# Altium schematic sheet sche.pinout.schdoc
size 297 x 209 mm; Width: 1170; Height: 825; Symbol: Sheet-Symbol_A4; Company: 嘉立创EDA; Version: V1.0; Page Size: A4; @Project Name: 木马派(Mumap) Linux卡片电脑-RV1106G; @Page Count: 10; @Update Date: 2024-12-29; @Create Date: 2024-11-25; @Schematic Name: Schematic1; @Page No: 5; Border: 1; Title Block Position: 3; Region Start: 1; X Region Count: 6; Y Region Count: 4; Blade Width: 10; Title Block: 1; @Board Name: NandFlash; @Create Time: 22:45:07; @Update Time: 16:11:56; @Page Name: FEPHY; Device: Sheet-Symbol_A4
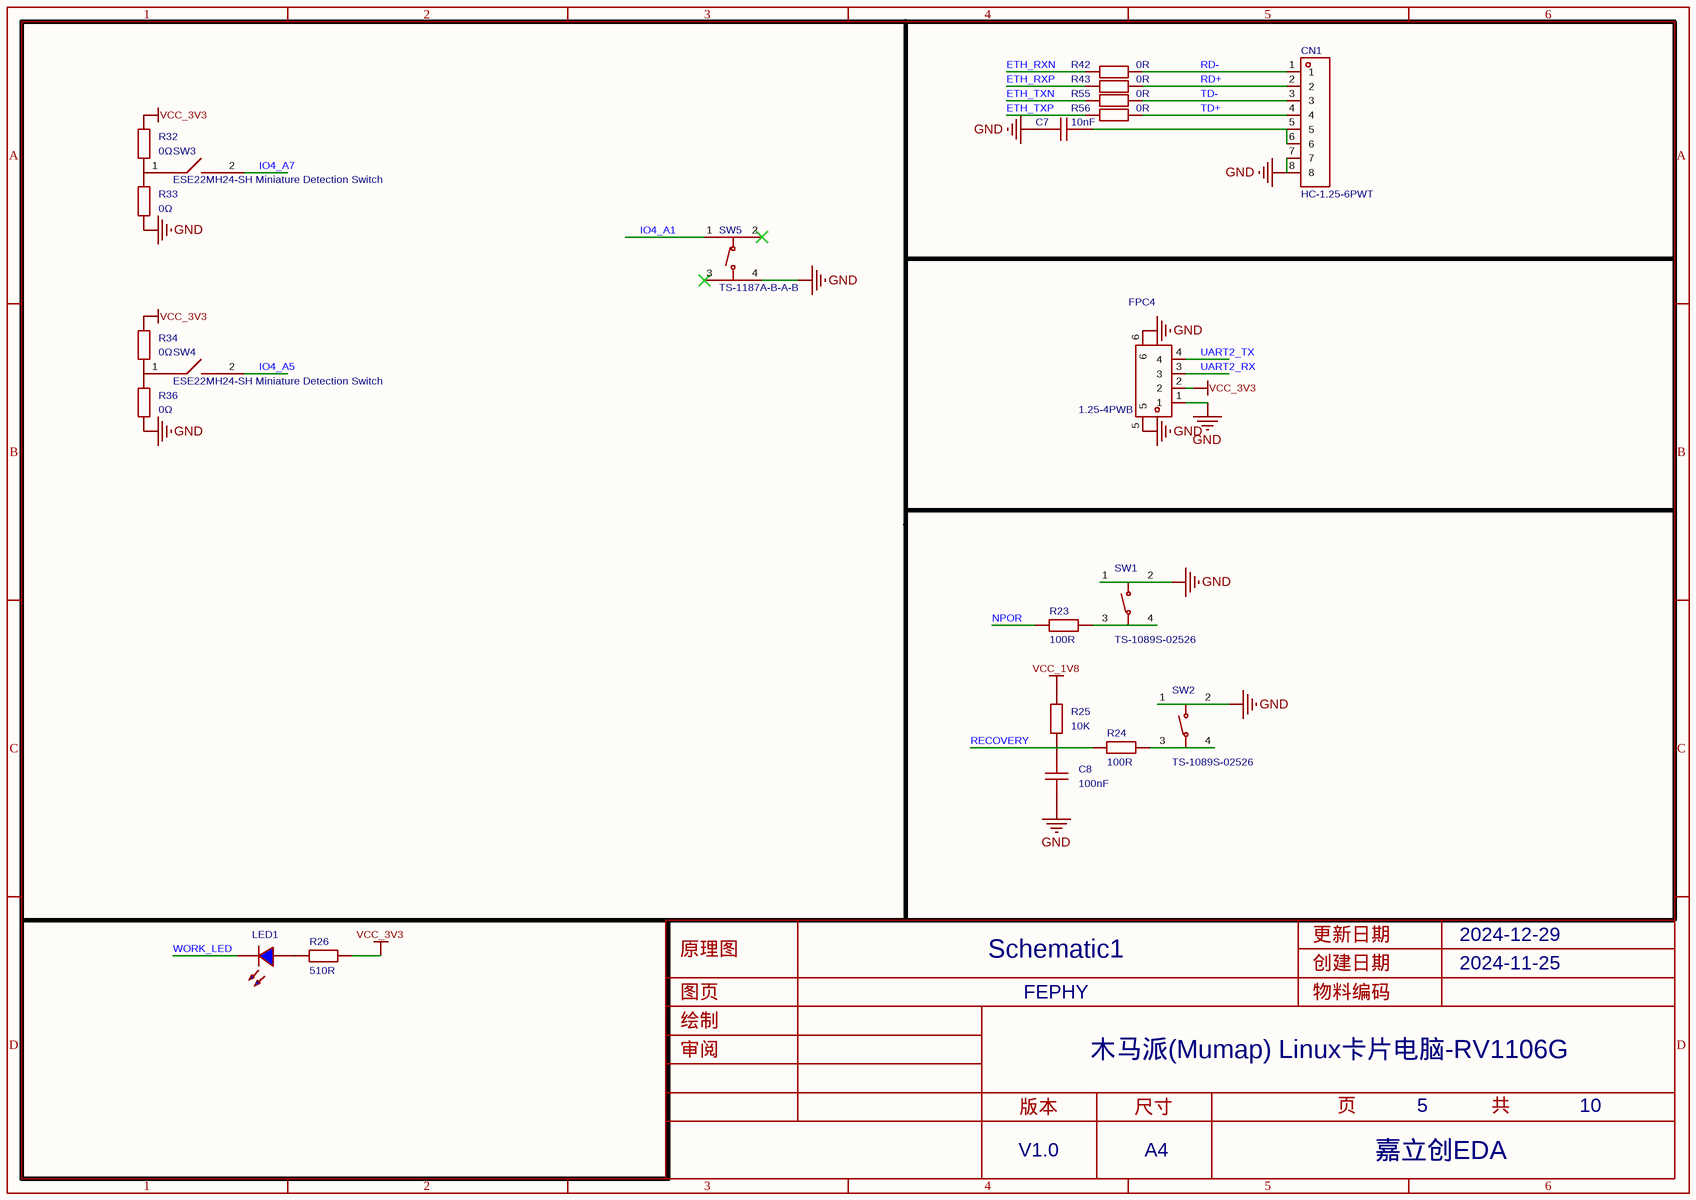
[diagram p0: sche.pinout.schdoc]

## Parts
C7  10nF  [C0402]
C8  100nF  [C0402]
CN1  HC-1.25-6PWT  [CONN-SMD_6P-P1.25_HC-1.25-6PWT]
FPC4  1.25-4PWB  [CONN-SMD_1.25-4PWB]
LED1  (no value)  [LED_0603]
R23  100R  [R0402]
R24  100R  [R0402]
R25  10K  [R0402]
R26  510R  [R0402]
R32  0Ω  [R0603]
R33  0Ω  [R0603]
R34  0Ω  [R0603]
R36  0Ω  [R0603]
R42  0R  [R0402]
R43  0R  [R0402]
R55  0R  [R0402]
R56  0R  [R0402]
SW1  TS-1089S-02526  [SW-SMD_4P-L4.2-W3.3-P2.15-LS5.1]
SW2  TS-1089S-02526  [SW-SMD_4P-L4.2-W3.3-P2.15-LS5.1]
SW3  ESE22MH24-SH Miniature Detection Switch  [SW-SMD_ESE22MH24]
SW4  ESE22MH24-SH Miniature Detection Switch  [SW-SMD_ESE22MH24]
SW5  TS-1187A-B-A-B  [SW-SMD_4P-L5.1-W5.1-P3.70-LS6.5-TL_H1.5]

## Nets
GND: C7.1 C8.1 CN1.7 CN1.8 FPC4.1 FPC4.5 FPC4.6 R33.1 R36.1 SW1.1 SW1.2 SW2.1 SW2.2 SW5.4(D)
VCC_1V8: R25.2
VCC_3V3: FPC4.2 R26.2 R32.2 R34.2
ETH_RXN: R42.1
ETH_RXP: R43.1
ETH_TXN: R55.1
ETH_TXP: R56.1
IO4_A1: SW5.1(A)
IO4_A5: SW4.2
IO4_A7: SW3.2
NPOR: R23.1
RD+: CN1.2 R43.2
RD-: CN1.1 R42.2
RECOVERY: C8.2 R24.1 R25.1
TD+: CN1.4 R56.2
TD-: CN1.3 R55.2
UART2_RX: FPC4.3
UART2_TX: FPC4.4
WORK_LED: LED1.1(C)
NetC7_2: C7.2 CN1.5 CN1.6
NetLED1_2: LED1.2(A) R26.1
NetR23_2: R23.2 SW1.3 SW1.4
NetR24_2: R24.2 SW2.3 SW2.4
NetR32_1: R32.1 R33.2 SW3.1
NetR34_1: R34.1 R36.2 SW4.1

Not connected (* = marked no-connect by the designer): SW5 2(B)* 3(C)*

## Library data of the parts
C7 C8 = CAP_0402: Symbol: CapAcitance; 3D Model: 36a51122f27c49738f86b3bfa98863e0; 3D Model Transform: 39.37,19.685,0,0,0,0,0,0,0; ConvertToPcb: yes; ModelName: C0402_L1.0-W0.5-H0.5
CN1 = HC-1.25-6PWT: 插针结构:1x6P;间距:1.25mm;安装方式:卧贴;参考系列:PicoBlade(MX 1.25);总PIN数:6P;排数:1;每排PIN数:6;行距:-;额定电流:1A;触头材质:黄铜;触头镀层:锡;工作温度:-40℃~+105℃;; Manufacturer: HCTL(华灿天禄); AddInBom: yes; ModelId: 759c9ac0920b4c9fa15d606e27a3b4ef0819f05c4eef4c71ace90d822a990e87; ModelTransform: 496.062,206.693,0,0,0,0,-0.002,-31.294,0; Pins Structure: 1x6P; Pitch: 1.25mm; Number of PINs Per Row: 6; Current Rating: 1A; Voltage Rating: 125V; Plastic Material: LCP; Flame Retardant Rating: UL94V-0; Supplementary Features: 辅助焊脚; Z-Height of the Board: 3.57mm; X-Length of Bottom Edge on Board (Spacing Line): 12.55mm; Y-Width of Bottom Edge on Board: 5.25mm
FPC4 = 1.25-4PWB: 插针结构:1x4P;间距:1.25mm;安装方式:卧贴;参考系列:PicoBlade(MX 1.25);总PIN数:4P;排数:1;每排PIN数:4;行距:-;额定电流:1A;触头材质:黄铜;触头镀层:锡;工作温度:-25℃~+85℃;; Manufacturer: DEALON(德艺隆); AddInBom: yes; ModelId: 1925d73ee5fd48ccb1364f2ca1c12f880819f05c4eef4c71ace90d822a990e87; ModelTransform: 393.7,206.693,0,0,0,0,0,-32.714,0; Pins Structure: 1x4P; Pitch: 1.25mm; Number of PINs Per Row: 4; Current Rating: 1A; Voltage Rating: 125V; Plastic Material: LCP; Flame Retardant Rating: UL94V-0; Supplementary Features: 辅助焊脚
LED1 = LED_0603-B: Symbol: LED_B; Convert to PCB: yes; 3D Model: eb8d964598f24248affda46f619856c5; 3D Model Transform: 63.1,31.6,23.7,0,0,0,0,0,0; ModelName: LED-0603_B
R23-R26 R42 R43 R55 R56 = Res_0402: Symbol: 电阻; 3D Model: 671aefced39d4c318694bba8bd8efd39; 3D Model Transform: 39.37,19.685,0,0,0,0,0,0.0005,0; ConvertToPcb: yes; ModelName: R0402_L1.0-W0.5-H0.5
R32-R34 R36 = RC0603FR-070RL: 电阻类型:厚膜电阻;阻值:0Ω;精度:±1%;功率:100mW;工作电压:75V;温度系数:-;; Manufacturer: YAGEO(国巨); AddInBom: yes; ModelId: fc143cca1e79419f9cd78b61e9279f080819f05c4eef4c71ace90d822a990e87; ModelTransform: 31.8897,63.7794,0,90,0,0,0,0,0; Tolerance: ±1%; Power(Watts): 100mW; Voltage-Supply(Max): 75V
SW1 SW2 = TS-1089S-02526: 电路结构:单刀单掷;按钮形状:椭圆形按钮;安装方式:立贴;开关长度:4.2mm;开关宽度:3.25mm;开关高度:2.5mm;触点电流:50mA;额定电压(DC):12V;带灯:-;机械寿命:-;; Manufacturer: XUNPU(讯普); 3D Model: 101da67941e24d4e9615179a94fc6132; 3D Model Transform: 204.724,127.9525,0,0,0,0,0,0,0; Circuit: 单刀单掷; Actuator Style: 椭圆形按钮; Switch Length: 4.2mm; Switch Width: 3.25mm; Switch Height: 2.5mm; Contact Current: 50mA; Voltage Rating (DC): 12V; AddInBom: yes; ModelName: SW-SMD_4P-L4.2-W3.3-H2.5-P2.15-LS5.1
SW3 SW4 = ESE22MH24-SH Miniature Detection Switch: 电路结构:单刀单掷;额定电流(DC):10mA;额定电压(DC):5V;工作寿命:5万次;; Manufacturer: SHOU HAN(首韩); AddInBom: yes; ModelId: 14551ff1b54d4140b62521d866b92d740819f05c4eef4c71ace90d822a990e87; ModelName: SW-SMD_ESE22MH24-L8.7-W5.7-H1.9-P3.5; ModelTransform: 224.409,338.95389,0,0,0,0,-0.041,139.764,-19.685; Circuit: 单刀单掷; Actuator Style: 角拨动; Switch Height: 2.1mm; Current Rating (DC): 10mA; Voltage Rating (DC): 5V; Life: 5万次
SW5 = TS-1187A-B-A-B: 电路结构:单刀单掷;按钮形状:圆形按钮;作用力:1.6N;安装方式:立贴;开关长度:5.1mm;开关宽度:5.1mm;开关高度:1.5mm;带支架:不带支架;触点电流:50mA;额定电压:12V;带灯:无;工作寿命:10万次;; Manufacturer: XKB Connection(中国星坤); AddInBom: yes; ModelId: 56992f66d31b474c84a0c3bd0a81f82f0819f05c4eef4c71ace90d822a990e87; ModelTransform: 255.905,204.76337,0,0,0,0,0,0,0; Circuit: 单刀单掷; Actuator Style: 圆形按钮; Operating Force: 1.6N; Switch Height: 1.5mm; with Bracket: 不带支架; Contact Current: 50mA; Voltage Rating: 12V; Actuator/Cap Color: 金色; With Lamp: 无; Life: 10万次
